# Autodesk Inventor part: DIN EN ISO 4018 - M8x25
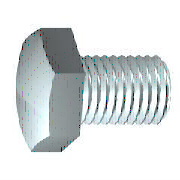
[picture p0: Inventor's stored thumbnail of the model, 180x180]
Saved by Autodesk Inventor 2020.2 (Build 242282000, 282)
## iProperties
Manager: www.cadconsulting.pl
Company: Fabian Stasiak CAD Consulting
Created: 2006-02
Part Number: DIN EN ISO 4018 - M8x25
Material: Stal, miękka
Description: Śruby z łbem sześciokątnym z gwintem do łba. Klasa dokładności C
Document SubType Name: Modeling
Standard: DIN EN ISO 4018
Designer: F.Stasiak
Standards Organization: DIN
Language: pl-PL
Size Designation: M8x25
Categories: <MemberInstance><Categories><Category DisplayName="Mocowania" InternalName="e4da775c-781d-43d5-af7c-5136215cf5a6" Mnemonic="FSTN"><Category DisplayName="Śruby"
Density: 7.86 g/cm^3
Appearance: Stal
Author: F.Stasiak
Subject: Zbiór ćwiczeń. Autodesk Inventor 2020. Kurs podstawowy
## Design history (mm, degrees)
node "WorkPlane1"
node "WorkPoint1"
node "MSC_A1"
node "MSC_PF1"
node "MSC_PT1"
node "Bryła1"
node "Korpusy bryłowe"
node "Korpusy powierzchniowe"
node "Szkic1"
sketch "Szkic2"
  geometry: L1 (-6.5, 3.753)-(-6.5, -3.753); L2 (0, 7.505)-(-6.5, 3.753); L3 (6.5, 3.753)-(0, 7.505); L4 (6.5, -3.753)-(6.5, 3.753); L5 (0, -7.505)-(6.5, -3.753); L6 (-6.5, -3.753)-(0, -7.505); C1 r 6.5 at (0, 0); 1 further point
  constraints: 12 end point, 6 tangent, 2 parallel, 2 vertical, 1 centre point
  dimensions: "d1" = 13 diameter of C1 (= ParS); "d29" = 0 distance of point (0, 0) C1.centre; "d30" = 0 distance of C1.centre point (0, 0)
extrude "Wyciągnięcie proste1" new body sketch "Szkic2" distance "d6" = 5.3 (= ParK); taper "d7" = 0 deg
revolve "Obrót1" stored, may be unused: angle "d14" = 360 deg
revolve "Obrót2" stored, may be unused: angle "d21" = 360 deg
chamfer "Faza1" distance "d22" = 0.625 (= 0.5 x PTC); stored, may be unused: second distance "d23" = 0.625 (= 0.5 x PTC), angle "d39" = 45 deg
fillet "Zaokrąglenie1" dims "d24" = 0.4 (= r)
feature "Gwint1" dims "d32" = 0, "b" = 22.5 (= NLG - 2 x PTC)
sketch "Szkic3"
  geometry: L1 (6.5, 5.3)-(7.605, 5.3); L2 (7.605, 4.662)-(6.5, 5.3); L3 (7.605, 5.3)-(7.605, 4.662); L4 (0, -0.53)-(0, 6.89) reference; L5 (7.505, 0)-(7.505, 5.3) reference
  constraints: 6 end point, 1 horizontal, 1 vertical
  dimensions: "d25" = 0.1 distance between parallel lines of L5 L3; "d26" = 0 distance from line of L5.end L1; "d27" = 60 deg angle of L3 L2; "d28" = 6.5 distance from line of L4 L1.start (= 0.5 x ParS)
sketch "Szkic4"
  geometry: L1 (0, -25)-(0, 0); L2 (-4, -25)-(0, -25); L3 (-4, 0)-(-4, -25); L4 (0, 0)-(-4, 0); L5 (0, -25)-(0, 0); L6 (-4.4, 0)-(1.2, 0) reference; L7 (0, -27.5)-(0, 7.5) reference
  constraints: 10 end point, 2 horizontal, 2 vertical
  dimensions: "d18" = 4 distance of L1.start L2.start (= 0.5 x NND); "d20" = 25 distance of L3.start L2.start (= NLG); "d33" = 0 distance between parallel lines of L7 L1; "d34" = 0 distance between parallel lines of L6 L4
other parameters: "NND" = 8 [user parameter; used in 2 equation terms], "NLG" = 25 [user parameter; used in 2 equation terms], "PTC" = 1.25 [user parameter; used in 3 equation terms], "ParK" = 5.3 [user parameter; used in 1 equation term], "ParS" = 13 [user parameter; used in 3 equation terms], "msp_es" = 7.50577 (= 0.577367 x ParS) [user parameter], "r" = 0.4 [user parameter; used in 1 equation term], "d2" = 15 (derived), "d4" = 17.32102 (derived), "d8" = 15 (derived), "d10" = 0 (derived), "d12" = 30 deg (derived), "d15" = 0 (derived), "d37" = 0, "d38" = 0, "d40" = 0, "d41" = 0, "d42" = 0, "THREADDIA" = 8 (= NND) [user parameter]
